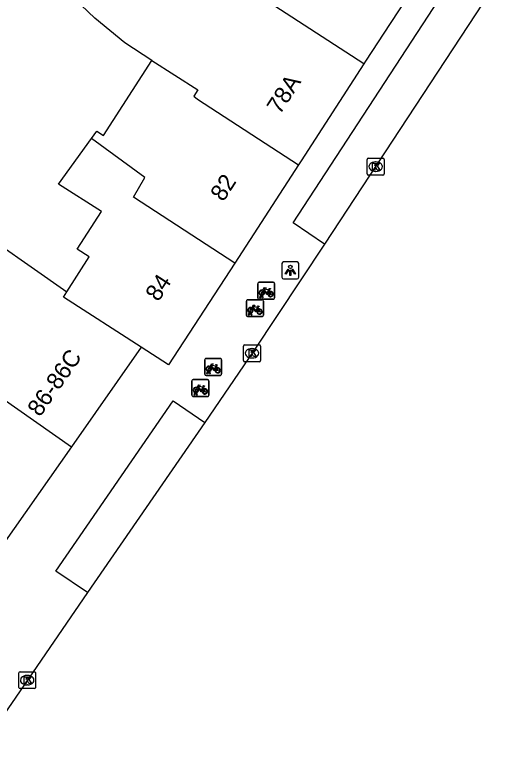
# Model space of a CAD drawing. Extents: x 160107 to 160928, y 382056 to 382918.
# Drawn here: x 160801.1 to 160829.73, y 382620.84 to 382664.5 of the extents above; entities that cross this region are included whole.
import ezdxf

# ---------------------------------------------------------------- set-up
doc = ezdxf.new("R2010")
doc.units = 0
for name, color, linetype in [('IMGEO_Fietsenrek', 7, 'Continuous'), ('IMGEO_Kolk', 7, 'Continuous'), ('IMGEO_Lichtpunt', 7, 'Continuous'), ('IMGEO_Pand', 7, 'Continuous'), ('IMGEO_Pand_nummerreeks', 7, 'Continuous'), ('IMGEO_Rijbaan_lokaal_gesloten', 7, 'Continuous'), ('IMGEO_Voetpad_open', 7, 'Continuous')]:
    doc.layers.add(name, color=color, linetype=linetype)

msp = doc.modelspace()

# ---------------------------------------------------------------- linework, layer by layer
at = {"layer": 'IMGEO_Fietsenrek'}
for p, q in [((160815.489, 382647.735), (160815.489, 382648.576)), ((160815.489, 382648.576), (160815.489, 382647.735)), ((160815.564, 382648.66), (160816.405, 382648.66)), ((160816.405, 382648.66), (160815.564, 382648.66)), ((160816.489, 382648.585), (160816.489, 382647.744)), ((160816.489, 382647.744), (160816.489, 382648.585)), ((160816.176, 382648.209), (160816.212, 382648.114)), ((160814.901, 382647.629), (160815.742, 382647.629)), ((160815.742, 382647.629), (160814.901, 382647.629)), ((160816.414, 382647.66), (160815.573, 382647.66)), ((160815.573, 382647.66), (160816.414, 382647.66)), ((160815.616, 382647.744), (160815.655, 382647.904)), ((160815.65, 382647.744), (160815.616, 382647.744)), ((160815.685, 382647.892), (160815.65, 382647.744)), ((160815.727, 382647.916), (160815.726, 382647.92)), ((160815.768, 382647.744), (160815.734, 382647.886)), ((160815.758, 382647.927), (160815.759, 382647.92)), ((160815.766, 382647.89), (160815.801, 382647.744)), ((160815.801, 382647.744), (160815.768, 382647.744)), ((160814.826, 382646.704), (160814.826, 382647.545)), ((160814.826, 382647.545), (160814.826, 382646.704)), ((160815.513, 382647.178), (160815.549, 382647.083)), ((160815.826, 382647.554), (160815.826, 382646.713)), ((160815.826, 382646.713), (160815.826, 382647.554)), ((160814.953, 382646.713), (160814.992, 382646.873)), ((160814.987, 382646.713), (160814.953, 382646.713)), ((160815.022, 382646.861), (160814.987, 382646.713)), ((160815.064, 382646.885), (160815.063, 382646.889)), ((160815.105, 382646.713), (160815.071, 382646.855)), ((160815.095, 382646.896), (160815.096, 382646.889)), ((160815.103, 382646.859), (160815.138, 382646.713)), ((160815.138, 382646.713), (160815.105, 382646.713)), ((160815.751, 382646.629), (160814.91, 382646.629)), ((160814.91, 382646.629), (160815.751, 382646.629)), ((160812.354, 382643.228), (160812.354, 382644.069)), ((160812.354, 382644.069), (160812.354, 382643.228)), ((160812.429, 382644.153), (160813.27, 382644.153)), ((160813.27, 382644.153), (160812.429, 382644.153)), ((160813.354, 382644.078), (160813.354, 382643.237)), ((160813.354, 382643.237), (160813.354, 382644.078)), ((160813.041, 382643.702), (160813.077, 382643.607)), ((160812.481, 382643.237), (160812.52, 382643.397)), ((160812.515, 382643.237), (160812.481, 382643.237)), ((160812.55, 382643.385), (160812.515, 382643.237)), ((160812.592, 382643.409), (160812.591, 382643.413)), ((160812.633, 382643.237), (160812.599, 382643.379)), ((160812.623, 382643.42), (160812.624, 382643.413)), ((160812.631, 382643.383), (160812.666, 382643.237)), ((160812.666, 382643.237), (160812.633, 382643.237)), ((160811.593, 382641.975), (160811.593, 382642.816)), ((160811.593, 382642.816), (160811.593, 382641.975)), ((160811.668, 382642.9), (160812.509, 382642.9)), ((160812.509, 382642.9), (160811.668, 382642.9)), ((160813.279, 382643.153), (160812.438, 382643.153)), ((160812.438, 382643.153), (160813.279, 382643.153)), ((160812.593, 382642.825), (160812.593, 382641.984)), ((160812.593, 382641.984), (160812.593, 382642.825)), ((160812.28, 382642.449), (160812.316, 382642.354)), ((160812.518, 382641.9), (160811.677, 382641.9)), ((160811.677, 382641.9), (160812.518, 382641.9)), ((160811.72, 382641.984), (160811.759, 382642.144)), ((160811.754, 382641.984), (160811.72, 382641.984)), ((160811.789, 382642.132), (160811.754, 382641.984)), ((160811.831, 382642.156), (160811.83, 382642.16)), ((160811.872, 382641.984), (160811.838, 382642.126)), ((160811.862, 382642.167), (160811.863, 382642.16)), ((160811.87, 382642.13), (160811.905, 382641.984)), ((160811.905, 382641.984), (160811.872, 382641.984))]:
    msp.add_line(p, q, dxfattribs=at)
for points in [[(160815.823, 382648.134), (160815.771, 382648.044), (160815.731, 382648.019), (160815.732, 382648.066), (160815.787, 382648.16)], [(160815.802, 382648.186), (160815.897, 382648.35), (160815.983, 382648.336), (160815.985, 382648.327), (160815.929, 382648.316), (160815.902, 382648.271), (160816.158, 382648.23)], [(160816.098, 382647.942), (160816.048, 382647.942), (160815.857, 382648.193), (160815.838, 382648.161)], [(160816.145, 382648.205), (160815.888, 382648.246), (160815.871, 382648.217), (160816.038, 382647.997), (160816.145, 382648.205)], [(160816.193, 382648.107), (160816.163, 382648.184), (160816.054, 382647.966), (160816.097, 382647.966)], [(160816.127, 382647.966), (160816.247, 382647.965), (160816.203, 382648.079)], [(160816.223, 382648.086), (160816.278, 382647.941), (160816.128, 382647.941)], [(160816.158, 382648.23), (160816.183, 382648.279), (160816.177, 382648.283), (160816.154, 382648.287), (160816.142, 382648.294), (160816.141, 382648.297), (160816.143, 382648.302), (160816.238, 382648.287), (160816.24, 382648.277), (160816.23, 382648.264), (160816.218, 382648.258), (160816.204, 382648.264), (160816.176, 382648.209)], [(160815.16, 382647.103), (160815.108, 382647.013), (160815.068, 382646.988), (160815.069, 382647.035), (160815.124, 382647.129)], [(160815.139, 382647.155), (160815.234, 382647.319), (160815.32, 382647.305), (160815.322, 382647.296), (160815.266, 382647.285), (160815.239, 382647.24), (160815.495, 382647.199)], [(160815.435, 382646.911), (160815.385, 382646.911), (160815.194, 382647.162), (160815.175, 382647.13)], [(160815.482, 382647.174), (160815.225, 382647.215), (160815.208, 382647.186), (160815.375, 382646.966), (160815.482, 382647.174)], [(160815.53, 382647.076), (160815.5, 382647.153), (160815.391, 382646.935), (160815.434, 382646.935)], [(160815.495, 382647.199), (160815.52, 382647.248), (160815.514, 382647.252), (160815.491, 382647.256), (160815.479, 382647.263), (160815.478, 382647.266), (160815.48, 382647.271), (160815.575, 382647.256), (160815.577, 382647.246), (160815.567, 382647.233), (160815.555, 382647.227), (160815.541, 382647.233), (160815.513, 382647.178)], [(160815.464, 382646.935), (160815.584, 382646.934), (160815.54, 382647.048)], [(160815.56, 382647.055), (160815.615, 382646.91), (160815.465, 382646.91)], [(160812.688, 382643.627), (160812.636, 382643.537), (160812.596, 382643.512), (160812.597, 382643.559), (160812.652, 382643.653)], [(160812.667, 382643.679), (160812.762, 382643.843), (160812.848, 382643.829), (160812.85, 382643.82), (160812.794, 382643.809), (160812.767, 382643.764), (160813.023, 382643.723)], [(160812.963, 382643.435), (160812.913, 382643.435), (160812.722, 382643.686), (160812.703, 382643.654)], [(160813.01, 382643.698), (160812.753, 382643.739), (160812.736, 382643.71), (160812.903, 382643.49), (160813.01, 382643.698)], [(160813.058, 382643.6), (160813.028, 382643.677), (160812.919, 382643.459), (160812.962, 382643.459)], [(160813.023, 382643.723), (160813.048, 382643.772), (160813.042, 382643.776), (160813.019, 382643.78), (160813.007, 382643.787), (160813.006, 382643.79), (160813.008, 382643.795), (160813.103, 382643.78), (160813.105, 382643.77), (160813.095, 382643.757), (160813.083, 382643.751), (160813.069, 382643.757), (160813.041, 382643.702)], [(160812.992, 382643.459), (160813.112, 382643.458), (160813.068, 382643.572)], [(160813.088, 382643.579), (160813.143, 382643.434), (160812.993, 382643.434)], [(160811.927, 382642.374), (160811.875, 382642.284), (160811.835, 382642.259), (160811.836, 382642.306), (160811.891, 382642.4)], [(160811.906, 382642.426), (160812.001, 382642.59), (160812.087, 382642.576), (160812.089, 382642.567), (160812.033, 382642.556), (160812.006, 382642.511), (160812.262, 382642.47)], [(160812.202, 382642.182), (160812.152, 382642.182), (160811.961, 382642.433), (160811.942, 382642.401)], [(160812.249, 382642.445), (160811.992, 382642.486), (160811.975, 382642.457), (160812.142, 382642.237), (160812.249, 382642.445)], [(160812.297, 382642.347), (160812.267, 382642.424), (160812.158, 382642.206), (160812.201, 382642.206)], [(160812.327, 382642.326), (160812.382, 382642.181), (160812.232, 382642.181)], [(160812.262, 382642.47), (160812.287, 382642.519), (160812.281, 382642.523), (160812.258, 382642.527), (160812.246, 382642.534), (160812.245, 382642.537), (160812.247, 382642.542), (160812.342, 382642.527), (160812.344, 382642.517), (160812.334, 382642.504), (160812.322, 382642.498), (160812.308, 382642.504), (160812.28, 382642.449)], [(160812.231, 382642.206), (160812.351, 382642.205), (160812.307, 382642.319)]]:
    msp.add_lwpolyline(points, dxfattribs=at)
for centre, radius, start, end in [((160815.567, 382648.582), 0.0779, 92.4484, 184.2845), ((160815.567, 382648.582), 0.0779, 92.4484, 184.2845), ((160816.411, 382648.582), 0.0779, 2.4484, 94.2845), ((160816.411, 382648.582), 0.0779, 2.4484, 94.2845), ((160815.729, 382648.045), 0.159, 62.6766, 242.1369), ((160815.729, 382648.045), 0.129, 63.3192, 238.903), ((160815.729, 382648.045), 0.129, 283.6043, 43.4302), ((160815.729, 382648.045), 0.159, 283.5766, 46.6042), ((160816.256, 382647.961), 0.159, 113.3408, 178.3217), ((160816.256, 382647.961), 0.159, 187.0065, 105.7708), ((160816.256, 382647.961), 0.129, 113.923, 177.9556), ((160816.256, 382647.961), 0.129, 188.6715, 104.5883), ((160814.904, 382647.551), 0.0779, 92.4484, 184.2845), ((160814.904, 382647.551), 0.0779, 92.4484, 184.2845), ((160815.567, 382647.738), 0.0779, 182.4484, 274.2845), ((160815.567, 382647.738), 0.0779, 182.4484, 274.2845), ((160815.709, 382647.916), 0.0499, 12.8025, 158.6934), ((160815.729, 382648.045), 0.159, 253.9967, 271.7867), ((160815.709, 382647.916), 0.0174, 12.8025, 163.4502), ((160815.729, 382648.045), 0.129, 253.415, 269.0204), ((160815.748, 382647.551), 0.0779, 2.4484, 94.2845), ((160815.748, 382647.551), 0.0779, 2.4484, 94.2845), ((160816.411, 382647.738), 0.0779, 272.4484, 4.2845), ((160816.411, 382647.738), 0.0779, 272.4484, 4.2845), ((160815.066, 382647.014), 0.159, 62.6766, 242.1369), ((160815.066, 382647.014), 0.129, 63.3192, 238.903), ((160815.066, 382647.014), 0.159, 283.5766, 46.6042), ((160814.904, 382646.707), 0.0779, 182.4484, 274.2845), ((160814.904, 382646.707), 0.0779, 182.4484, 274.2845), ((160815.046, 382646.885), 0.0499, 12.8025, 158.6934), ((160815.066, 382647.014), 0.159, 253.9967, 271.7867), ((160815.046, 382646.885), 0.0174, 12.8025, 163.4502), ((160815.066, 382647.014), 0.129, 253.415, 269.0204), ((160815.066, 382647.014), 0.129, 283.6043, 43.4302), ((160815.593, 382646.93), 0.159, 113.3408, 178.3217), ((160815.593, 382646.93), 0.159, 187.0065, 105.7708), ((160815.593, 382646.93), 0.129, 113.923, 177.9556), ((160815.593, 382646.93), 0.129, 188.6715, 104.5883), ((160815.748, 382646.707), 0.0779, 272.4484, 4.2845), ((160815.748, 382646.707), 0.0779, 272.4484, 4.2845), ((160812.432, 382644.075), 0.0779, 92.4484, 184.2845), ((160812.432, 382644.075), 0.0779, 92.4484, 184.2845), ((160813.276, 382644.075), 0.0779, 2.4484, 94.2845), ((160813.276, 382644.075), 0.0779, 2.4484, 94.2845), ((160812.594, 382643.538), 0.159, 62.6766, 242.1369), ((160812.594, 382643.538), 0.129, 63.3192, 238.903), ((160812.594, 382643.538), 0.159, 283.5766, 46.6042), ((160812.432, 382643.231), 0.0779, 182.4484, 274.2845), ((160812.432, 382643.231), 0.0779, 182.4484, 274.2845), ((160812.574, 382643.409), 0.0499, 12.8025, 158.6934), ((160812.594, 382643.538), 0.159, 253.9967, 271.7867), ((160812.574, 382643.409), 0.0174, 12.8025, 163.4502), ((160812.594, 382643.538), 0.129, 253.415, 269.0204), ((160812.594, 382643.538), 0.129, 283.6043, 43.4302), ((160813.121, 382643.454), 0.159, 113.3408, 178.3217), ((160813.121, 382643.454), 0.159, 187.0065, 105.7708), ((160813.121, 382643.454), 0.129, 113.923, 177.9556), ((160813.121, 382643.454), 0.129, 188.6715, 104.5883), ((160813.276, 382643.231), 0.0779, 272.4484, 4.2845), ((160813.276, 382643.231), 0.0779, 272.4484, 4.2845), ((160811.671, 382642.822), 0.0779, 92.4484, 184.2845), ((160811.671, 382642.822), 0.0779, 92.4484, 184.2845), ((160812.515, 382642.822), 0.0779, 2.4484, 94.2845), ((160812.515, 382642.822), 0.0779, 2.4484, 94.2845), ((160811.833, 382642.285), 0.159, 62.6766, 242.1369), ((160811.833, 382642.285), 0.129, 63.3192, 238.903), ((160811.833, 382642.285), 0.129, 283.6043, 43.4302), ((160811.833, 382642.285), 0.159, 283.5766, 46.6042), ((160812.36, 382642.201), 0.159, 113.3408, 178.3217), ((160812.36, 382642.201), 0.159, 187.0065, 105.7708), ((160812.36, 382642.201), 0.129, 188.6715, 104.5883), ((160811.671, 382641.978), 0.0779, 182.4484, 274.2845), ((160811.671, 382641.978), 0.0779, 182.4484, 274.2845), ((160811.813, 382642.156), 0.0499, 12.8025, 158.6934), ((160811.833, 382642.285), 0.159, 253.9967, 271.7867), ((160811.813, 382642.156), 0.0174, 12.8025, 163.4502), ((160811.833, 382642.285), 0.129, 253.415, 269.0204), ((160812.36, 382642.201), 0.129, 113.923, 177.9556), ((160812.515, 382641.978), 0.0779, 272.4484, 4.2845), ((160812.515, 382641.978), 0.0779, 272.4484, 4.2845)]:
    msp.add_arc(centre, radius, start, end, dxfattribs=at)
at = {"layer": 'IMGEO_Kolk'}
for p, q in [((160821.972, 382655.083), (160821.972, 382655.935)), ((160822.047, 382656.009), (160822.899, 382656.009)), ((160822.973, 382655.935), (160822.973, 382655.083)), ((160822.46, 382655.789), (160822.485, 382655.789)), ((160822.899, 382655.009), (160822.047, 382655.009)), ((160822.483, 382655.229), (160822.458, 382655.229)), ((160814.73, 382644.96), (160815.582, 382644.96)), ((160814.655, 382644.034), (160814.655, 382644.886)), ((160815.143, 382644.74), (160815.168, 382644.74)), ((160815.656, 382644.886), (160815.656, 382644.034)), ((160815.166, 382644.18), (160815.141, 382644.18)), ((160815.582, 382643.96), (160814.73, 382643.96)), ((160801.342, 382624.682), (160801.342, 382625.534)), ((160801.417, 382625.608), (160802.269, 382625.608)), ((160801.83, 382625.388), (160801.855, 382625.388)), ((160802.343, 382625.534), (160802.343, 382624.682)), ((160802.269, 382624.608), (160801.417, 382624.608)), ((160801.853, 382624.828), (160801.828, 382624.828))]:
    msp.add_line(p, q, dxfattribs=at)
for points in [[(160821.972, 382655.083), (160821.972, 382655.935)], [(160822.047, 382656.009), (160822.899, 382656.009)], [(160822.973, 382655.935), (160822.973, 382655.083)], [(160822.293, 382655.709), (160822.416, 382655.709), (160822.416, 382655.558), (160822.546, 382655.709), (160822.71, 382655.709), (160822.564, 382655.558), (160822.717, 382655.309), (160822.565, 382655.309), (160822.48, 382655.473), (160822.416, 382655.406), (160822.416, 382655.309), (160822.293, 382655.309), (160822.293, 382655.709)], [(160822.899, 382655.009), (160822.047, 382655.009)], [(160814.73, 382644.96), (160815.582, 382644.96)], [(160814.655, 382644.034), (160814.655, 382644.886)], [(160814.976, 382644.66), (160815.099, 382644.66), (160815.099, 382644.509), (160815.229, 382644.66), (160815.393, 382644.66), (160815.247, 382644.509), (160815.4, 382644.26), (160815.248, 382644.26), (160815.163, 382644.424), (160815.099, 382644.357), (160815.099, 382644.26), (160814.976, 382644.26), (160814.976, 382644.66)], [(160815.656, 382644.886), (160815.656, 382644.034)], [(160815.582, 382643.96), (160814.73, 382643.96)], [(160801.342, 382624.682), (160801.342, 382625.534)], [(160801.417, 382625.608), (160802.269, 382625.608)], [(160801.663, 382625.308), (160801.786, 382625.308), (160801.786, 382625.157), (160801.916, 382625.308), (160802.08, 382625.308), (160801.934, 382625.157), (160802.087, 382624.908), (160801.935, 382624.908), (160801.85, 382625.072), (160801.786, 382625.005), (160801.786, 382624.908), (160801.663, 382624.908), (160801.663, 382625.308)], [(160802.343, 382625.534), (160802.343, 382624.682)], [(160802.269, 382624.608), (160801.417, 382624.608)]]:
    msp.add_lwpolyline(points, dxfattribs=at)
for centre, start, end in [((160822.049, 382655.933), 91.552, 178.448), ((160822.049, 382655.933), 91.552, 178.448), ((160822.897, 382655.933), 1.552, 88.448), ((160822.897, 382655.933), 1.552, 88.448), ((160822.049, 382655.085), 181.552, 268.448), ((160822.049, 382655.085), 181.552, 268.448), ((160822.897, 382655.085), 271.552, 358.448), ((160822.897, 382655.085), 271.552, 358.448), ((160814.732, 382644.884), 91.552, 178.448), ((160814.732, 382644.884), 91.552, 178.448), ((160815.58, 382644.884), 1.552, 88.448), ((160815.58, 382644.884), 1.552, 88.448), ((160814.732, 382644.036), 181.552, 268.448), ((160814.732, 382644.036), 181.552, 268.448), ((160815.58, 382644.036), 271.552, 358.448), ((160815.58, 382644.036), 271.552, 358.448), ((160801.419, 382625.532), 91.552, 178.448), ((160801.419, 382625.532), 91.552, 178.448), ((160802.267, 382625.532), 1.552, 88.448), ((160802.267, 382625.532), 1.552, 88.448), ((160801.419, 382624.684), 181.552, 268.448), ((160801.419, 382624.684), 181.552, 268.448), ((160802.267, 382624.684), 271.552, 358.448), ((160802.267, 382624.684), 271.552, 358.448)]:
    msp.add_arc(centre, 0.0765, start, end, dxfattribs=at)
for centre, major_axis, ratio, start_param, end_param in [((160822.459, 382655.509), (-0.387, 0.002), 0.722429, 4.712389, 7.853982), ((160822.484, 382655.509), (-0.39, 0.002), 0.717154, 1.570796, 4.712389), ((160815.142, 382644.46), (-0.387, 0.002), 0.722429, 4.712389, 7.853982), ((160815.167, 382644.46), (-0.39, 0.002), 0.717154, 1.570796, 4.712389), ((160801.829, 382625.108), (-0.387, 0.002), 0.722429, 4.712389, 7.853982), ((160801.854, 382625.108), (-0.39, 0.002), 0.717154, 1.570796, 4.712389)]:
    msp.add_ellipse(centre, major_axis=major_axis, ratio=ratio, start_param=start_param, end_param=end_param, dxfattribs=at)
at = {"layer": 'IMGEO_Lichtpunt'}
for p, q in [((160816.923, 382649.77), (160816.923, 382648.963)), ((160816.923, 382649.77), (160816.923, 382648.963)), ((160817.825, 382649.865), (160817.017, 382649.865)), ((160817.825, 382649.865), (160817.017, 382649.865)), ((160817.919, 382648.963), (160817.919, 382649.77)), ((160817.919, 382648.963), (160817.919, 382649.77)), ((160817.017, 382648.869), (160817.825, 382648.869)), ((160817.017, 382648.869), (160817.825, 382648.869))]:
    msp.add_line(p, q, dxfattribs=at)
for points in [[(160817.297, 382649.434), (160817.336, 382649.406), (160817.148, 382649.144), (160817.11, 382649.171), (160817.297, 382649.434)], [(160817.399, 382649.386), (160817.446, 382649.386), (160817.446, 382649.064), (160817.399, 382649.064), (160817.399, 382649.386)], [(160817.509, 382649.406), (160817.547, 382649.433), (160817.734, 382649.171), (160817.695, 382649.143), (160817.509, 382649.406)]]:
    msp.add_lwpolyline(points, dxfattribs=at)
msp.add_circle((160817.422, 382649.568), 0.0994, dxfattribs=at)
for centre, start, end in [((160817.017, 382649.77), 90, 180), ((160817.017, 382649.77), 90, 180), ((160817.825, 382649.77), 0, 90), ((160817.825, 382649.77), 0, 90), ((160817.017, 382648.963), 180, 270), ((160817.017, 382648.963), 180, 270), ((160817.825, 382648.963), 270, 0), ((160817.825, 382648.963), 270, 360)]:
    msp.add_arc(centre, 0.0946, start, end, dxfattribs=at)
at = {"layer": 'IMGEO_Pand'}
for points in [[(160809.226, 382661.801), (160807.624, 382662.832), (160805.852, 382664.303), (160800.044, 382669.827)], [(160821.774, 382661.597), (160815.776, 382665.498), (160815.629, 382665.629), (160811.692, 382669.149)], [(160825.508, 382667.307), (160823.328, 382663.975), (160821.871, 382661.747), (160821.774, 382661.597)], [(160785.069, 382654.734), (160786.338, 382656.69), (160782.806, 382659.883), (160785.595, 382663.742), (160788.911, 382660.658), (160798.037, 382652.404), (160804.186, 382648.094)], [(160805.646, 382657.17), (160805.963, 382657.609), (160806.357, 382657.355), (160809.226, 382661.801)], [(160809.226, 382661.801), (160811.951, 382660.046), (160811.713, 382659.676), (160811.925, 382659.508), (160817.908, 382655.617)], [(160821.774, 382661.597), (160818.057, 382655.846), (160817.908, 382655.617)], [(160804.186, 382648.094), (160805.519, 382650.163), (160804.802, 382650.625), (160806.234, 382652.848), (160803.703, 382654.479), (160805.646, 382657.17)], [(160814.13, 382649.8), (160808.143, 382653.695), (160808.797, 382654.861), (160805.646, 382657.17)], [(160817.908, 382655.617), (160814.13, 382649.8)], [(160785.069, 382654.734), (160796.043, 382644.814), (160804.459, 382638.914)], [(160814.13, 382649.8), (160810.216, 382643.775), (160808.597, 382644.818)], [(160808.597, 382644.818), (160803.99, 382647.79), (160804.186, 382648.094)], [(160808.597, 382644.818), (160804.459, 382638.914)], [(160804.459, 382638.914), (160800.424, 382633.157)]]:
    msp.add_lwpolyline(points, dxfattribs=at)
at = {"layer": 'IMGEO_Rijbaan_lokaal_gesloten'}
for points in [[(160829.732, 382666.583), (160819.446, 382650.913)], [(160819.446, 382650.913), (160815.241, 382644.584), (160812.358, 382640.352)], [(160812.358, 382640.352), (160805.417, 382630.29)], [(160805.417, 382630.29), (160798.913, 382620.841)]]:
    msp.add_lwpolyline(points, dxfattribs=at)
at = {"layer": 'IMGEO_Voetpad_open'}
for points in [[(160819.446, 382650.913), (160817.594, 382652.178), (160827.814, 382667.842), (160829.732, 382666.583)], [(160805.417, 382630.29), (160803.544, 382631.56), (160810.483, 382641.65), (160812.358, 382640.352)]]:
    msp.add_lwpolyline(points, dxfattribs=at)

# ---------------------------------------------------------------- texts
at = {"layer": 'IMGEO_Pand_nummerreeks'}
for s, rotation, p in [('78A', 57.1191, (160816.801, 382658.546)), ('82', 56.9933, (160813.454, 382653.385)), ('84', 56.9933, (160809.61, 382647.467)), ('86-86C', 54.9753, (160802.597, 382640.648))]:
    msp.add_text(s, height=1, rotation=rotation, dxfattribs=at).set_placement(p)

doc.saveas('drawing.dxf')
